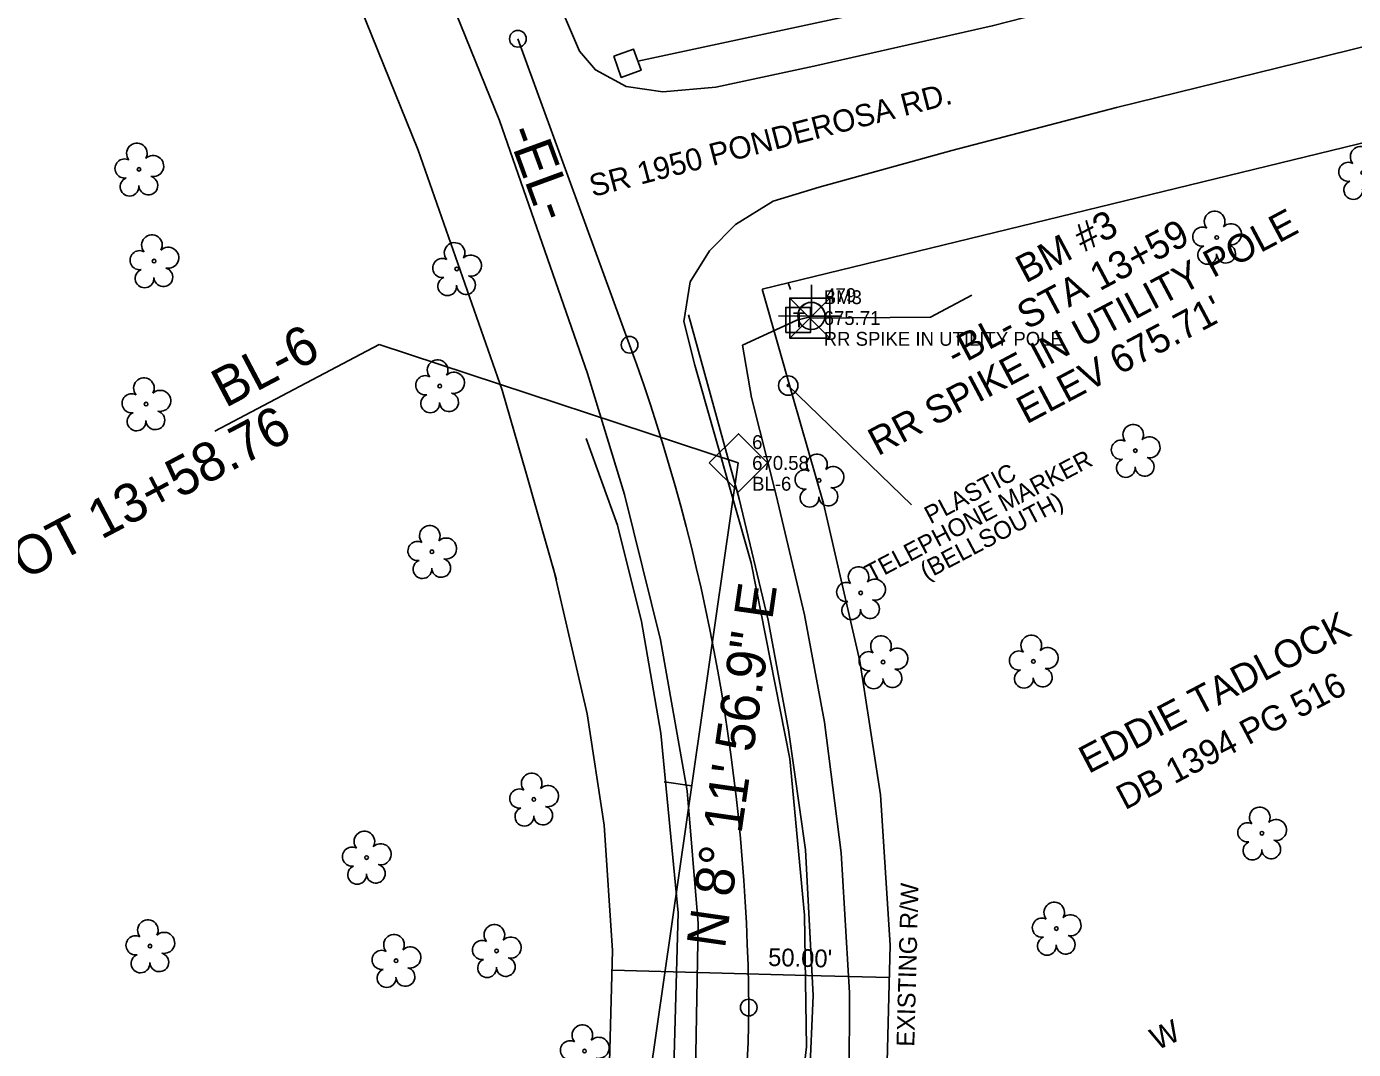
# Model space of a CAD drawing. Extents: x 1380524 to 1382335, y 594765 to 596944.
# Drawn here: x 1381752.4 to 1381991.4, y 595723.8 to 595908.1 of the extents above; entities that cross this region are included whole.
import ezdxf

# ---------------------------------------------------------------- set-up
doc = ezdxf.new("R2010")
doc.units = 0
for name, color, linetype in [('CTL Bench Mark CELL', 7, 'Continuous'), ('CTL Bench Mark Cogo Comment', 7, 'Continuous'), ('CTL Bench Mark Cogo Elevation', 7, 'Continuous'), ('CTL Bench Mark Cogo Number', 7, 'Continuous'), ('CTL Bench Mark Leader', 7, 'Continuous'), ('CTL Bench Mark Text', 7, 'Continuous'), ('CTL Supplemental Horizontal and Vertical Cogo Comment', 7, 'Continuous'), ('CTL Supplemental Horizontal and Vertical Cogo Elevation', 7, 'Continuous'), ('Exist Horizontal Alignment', 7, 'Continuous'), ('Exist Horizontal Alignment Direction Label', 7, 'Continuous'), ('Exist Horizontal Alignment Station Label', 7, 'Continuous'), ('Exist Horizontal Baseline Alignment', 7, 'Continuous'), ('Exist Horizontal Baseline Alignment Direction Label', 7, 'Continuous'), ('Exist Horizontal Baseline Alignment Station Label', 7, 'Continuous'), ('Exist Horizontal Baseline Alignment Tick small', 7, 'Continuous'), ('Exist Other Culture Fence Line', 7, 'Continuous'), ('Exist Other Culture Well Text', 7, 'Continuous'), ('Exist Right of Way Line', 7, 'Continuous'), ('Exist Right of Way Line Text', 7, 'Continuous'), ('Exist Roads EOP', 7, 'Continuous'), ('Exist Roads Soil', 7, 'Continuous'), ('Exist Structure Minor Pipes CMP 18 Inch', 7, 'Continuous'), ('Exist Utilities Gas UG Line SUE Text', 7, 'Continuous'), ('Exist Utilities Other Located Object Leader', 7, 'Continuous'), ('Exist Utilities Power Tower CELL', 7, 'Continuous'), ('Exist Utilities Telephone Pedestal CELL', 7, 'Continuous'), ('Exist Utilities Telephone UG Cable', 7, 'Continuous'), ('Exist Vegetation Tree CELL', 7, 'Continuous'), ('Exist Vertical Profile Vertical Axis Label', 7, 'Continuous'), ('Prop Drainage Ditch Flow Line', 7, 'Continuous'), ('Prop Drainage Structure Pipe Elbow Label', 7, 'Continuous'), ('Prop Earthen Structure Cut Ditch Special Detail CELL', 7, 'Continuous'), ('Prop Earthen Structure Ditch Flow Line', 7, 'Continuous'), ('Prop Erosion Rip Rap At Embankment Detail CELL', 7, 'Continuous'), ('Prop SS Cut Line', 7, 'Continuous'), ('Scratch_Level_6', 7, 'Continuous')]:
    doc.layers.add(name, color=color, linetype=linetype)

# ---------------------------------------------------------------- blocks, each defined once
blk = doc.blocks.new('EXIST VEGETATION TREE')
at = {"layer": 'Prop Erosion Rip Rap At Embankment Detail CELL'}
blk.add_line((0, 0), (0, 0), dxfattribs=at)
blk.add_circle((0, 0), 0.00652, dxfattribs=at)
for centre, radius, start, end in [((-0.0077, 0.0575), 0.0371, 330.1651, 219.7134), ((0.051, 0.0118), 0.038, 257.1011, 134.1999), ((-0.0521, 0.0031), 0.0345, 62.6636, 279.3457), ((-0.0341, -0.0624), 0.0338, 111.5671, 6.231), ((0.0335, -0.058), 0.034, 181.2822, 74.56)]:
    blk.add_arc(centre, radius, start, end, dxfattribs=at)
blk = doc.blocks.new('EXIST UTILITIES POWER JOINT USE TELEPHONE')
at = {"layer": 'Exist Utilities Gas UG Line SUE Text'}
blk.add_line((0, 0), (0, 0), dxfattribs=at)
blk.add_lwpolyline([(-0.1188, 0), (0.108, -0.0008), (0, -0.0004), (0, 0.1125)], dxfattribs=at)
blk.add_circle((0, 0.0001), 0.049, dxfattribs=at)
blk = doc.blocks.new('EXIST UTILITIES TELEPHONE PEDESTAL')
at = {"layer": 'Exist Utilities Telephone Pedestal CELL'}
blk.add_line((0, 0), (0, 0), dxfattribs=at)
blk.add_lwpolyline([(-0.0545, -0.0565), (0.0574, -0.0565), (0.0574, 0.0554), (-0.0545, 0.0554), (-0.0545, -0.0565)], dxfattribs=at)
blk.add_text('T', height=0.0684, dxfattribs=at).set_placement((-0.0226, -0.0343))
blk = doc.blocks.new('EXIST UTILITIES OTHER LOCATED OBJECT')
at = {"layer": 'Prop Earthen Structure Cut Ditch Special Detail CELL'}
for radius in [0.0436, 0.0048]:
    blk.add_circle((0, 0), radius, dxfattribs=at)

msp = doc.modelspace()

# ---------------------------------------------------------------- linework, layer by layer
at = {"layer": 'CTL Bench Mark CELL'}
msp.add_line((1381893.47, 595855.57), (1381893.47, 595855.57), dxfattribs=at)
msp.add_lwpolyline([(1381889.87, 595859.16), (1381897.06, 595859.16), (1381897.06, 595851.97), (1381889.87, 595851.97)], close=True, dxfattribs=at)
for points in [[(1381897.06, 595859.16), (1381889.87, 595851.97), (1381893.47, 595855.57), (1381897.06, 595851.97), (1381889.87, 595859.16)], [(1381893.47, 595855.57), (1381897.06, 595859.16), (1381889.87, 595859.16), (1381893.47, 595855.57)], [(1381893.47, 595855.57), (1381889.87, 595851.97), (1381897.06, 595851.97), (1381893.47, 595855.57)]]:
    msp.add_lwpolyline(points, dxfattribs=at)
at = {"layer": 'CTL Bench Mark Leader'}
msp.add_lwpolyline([(1381893.47, 595855.57), (1381915.22, 595855.75), (1381922.66, 595859.66)], dxfattribs=at)
at = {"layer": 'Exist Horizontal Alignment'}
msp.add_line((1381861, 595850.75), (1381840.88, 595905.87), dxfattribs=at)
msp.add_line((1381861, 595850.75), (1381840.88, 595905.87), dxfattribs=at)
msp.add_line((1381861, 595850.75), (1381840.88, 595905.87), dxfattribs=at)
msp.add_line((1381861, 595850.75), (1381840.88, 595905.87), dxfattribs=at)
msp.add_line((1381861, 595850.75), (1381840.88, 595905.87), dxfattribs=at)
for centre, radius, start, end in [((1381528.59, 595729.39), 353.88, 0.3204, 20.0563), ((1381528.59, 595729.39), 353.88, 0.3204, 20.0563), ((1381528.59, 595729.39), 353.88, 0.3204, 20.0563), ((1381732.46, 595730.53), 150, 321.7878, 0.3204), ((1381732.46, 595730.53), 150, 321.7878, 0.3204), ((1381732.46, 595730.53), 150, 321.7878, 0.3204)]:
    msp.add_arc(centre, radius, start, end, dxfattribs=at)
at = {"layer": 'Exist Horizontal Alignment Station Label'}
for centre in [(1381840.88, 595905.87), (1381861, 595850.75), (1381882.46, 595731.37)]:
    msp.add_circle(centre, 1.5, dxfattribs=at)
at = {"layer": 'Exist Horizontal Baseline Alignment'}
msp.add_line((1381849.7, 595615.17), (1381880.58, 595829.47), dxfattribs=at)
at = {"layer": 'Exist Horizontal Baseline Alignment Station Label'}
for p, q in [((1381815.89, 595850.81), (1381786.27, 595835.2)), ((1381880.58, 595829.47), (1381815.89, 595850.81))]:
    msp.add_line(p, q, dxfattribs=at)
at = {"layer": 'Exist Horizontal Baseline Alignment Tick small'}
msp.add_line((1381872.2, 595771.32), (1381867.25, 595772.03), dxfattribs=at)
at = {"layer": 'Exist Other Culture Fence Line'}
for q in [(1381893.75, 595861.56), (1381893.75, 595855.94)]:
    msp.add_line((1381893.75, 595855.94), q, dxfattribs=at)
msp.add_circle((1381893.75, 595855.94), 2.45, dxfattribs=at)
at = {"layer": 'Exist Roads EOP'}
for p, q in [((1381884.86, 595860.79), (1382255.74, 595951.12)), ((1381842.35, 595827.6), (1381838.07, 595842.58)), ((1381895.92, 595822.17), (1381890.42, 595841.37)), ((1381847.85, 595808.4), (1381842.35, 595827.6))]:
    msp.add_line(p, q, dxfattribs=at)
for points in [[(1381756.61, 596057.82), (1381792.83, 595960.19), (1381822.94, 595885.83), (1381838.07, 595842.58)], [(1381884.86, 595860.79), (1381890.42, 595841.37)], [(1381889.57, 595861.92), (1381889.98, 595860.73)], [(1381895.92, 595822.17), (1381902.47, 595793.76), (1381906.2, 595769.7), (1381907.97, 595742.61), (1381907.23, 595714.6), (1381902.73, 595686.65), (1381893.97, 595660.65), (1381884.45, 595642.32), (1381871.1, 595622.85), (1381855.36, 595606.07), (1381838.64, 595592.06), (1381819.68, 595578.62), (1381797.68, 595564.39), (1381777.69, 595551.91), (1381745.42, 595532.92), (1381704.18, 595509.33)], [(1381847.19, 595810.94), (1381853.34, 595784.3), (1381856.45, 595764.22), (1381857.93, 595741.64), (1381857.34, 595719.26), (1381854.03, 595698.69), (1381847.82, 595680.28), (1381841.48, 595668.07), (1381832.02, 595654.27), (1381820.95, 595642.47), (1381808.08, 595631.69), (1381791.64, 595620.03), (1381770.85, 595606.59), (1381751.76, 595594.66), (1381720.33, 595576.17), (1381679.35, 595552.72)]]:
    msp.add_lwpolyline(points, dxfattribs=at)
at = {"layer": 'Exist Utilities Other Located Object Leader'}
msp.add_lwpolyline([(1381889.58, 595843.41), (1381911.82, 595821.92)], dxfattribs=at)
at = {"layer": 'Exist Utilities Power Tower CELL'}
for p in [(1381857.84, 595738.09), (1381907.82, 595736.76)]:
    msp.add_line(p, (1381893.04, 595737.15), dxfattribs=at)
at = {"layer": 'Exist Utilities Telephone UG Cable'}
for p, q in [((1381880.73, 595823.01), (1381871.64, 595856.13)), ((1381891.13, 595855.21), (1381894.01, 595855.88)), ((1381881.35, 595850.66), (1381891.13, 595855.21)), ((1381882.97, 595841.27), (1381881.35, 595850.66)), ((1381887.4, 595823.66), (1381882.97, 595841.27)), ((1381858.83, 595818.25), (1381853.18, 595833.86)), ((1381885.96, 595801.15), (1381880.73, 595823.01)), ((1381892.51, 595802.1), (1381887.4, 595823.66)), ((1381863.12, 595800.9), (1381858.83, 595818.25)), ((1381866.66, 595780.77), (1381863.12, 595800.9)), ((1381889.63, 595781.4), (1381885.96, 595801.15)), ((1381896.12, 595782.79), (1381892.51, 595802.1)), ((1381892.7, 595759.75), (1381889.63, 595781.4)), ((1381899.13, 595759.23), (1381896.12, 595782.79)), ((1381869.73, 595748.41), (1381866.66, 595780.77)), ((1381894.08, 595733.51), (1381892.7, 595759.75)), ((1381900.64, 595734.04), (1381899.13, 595759.23)), ((1381868.99, 595720.53), (1381869.73, 595748.41)), ((1381892.86, 595705.57), (1381894.08, 595733.51)), ((1381900.56, 595709.92), (1381900.64, 595734.04))]:
    msp.add_line(p, q, dxfattribs=at)
at = {"layer": 'Prop Drainage Ditch Flow Line'}
msp.add_lwpolyline([(1381858.14, 595902.71), (1381861.72, 595903.98), (1381863.07, 595900.2), (1381859.49, 595898.92)], close=True, dxfattribs=at)
at = {"layer": 'Prop Drainage Structure Pipe Elbow Label'}
msp.add_lwpolyline([(1381862.51, 595901.85), (1381933.42, 595917.07)], dxfattribs=at)
at = {"layer": 'Prop Earthen Structure Ditch Flow Line'}
msp.add_line((1381860.1, 595823.76), (1381853.43, 595845.6), dxfattribs=at)
for points in [[(1381771.25, 596063.05), (1381807.38, 595965.66), (1381837.55, 595891.15), (1381853.43, 595845.6)], [(1382091.45, 595950.01), (1382040.09, 595937.29), (1382004.26, 595928.01), (1381958.8, 595916.53), (1381926.33, 595908.18), (1381894.21, 595900.91), (1381876.52, 595897.14), (1381867, 595896.29), (1381860.37, 595897.28), (1381854.86, 595900.27), (1381851.95, 595903.63), (1381839.95, 595931.67), (1381826.08, 595965.16), (1381814.38, 595994.56), (1381803.44, 596023.95), (1381793.75, 596050.62), (1381789.17, 596063.13)], [(1381875.4, 595867.69), (1381880.08, 595872.41), (1381886.87, 595876.59), (1381895.15, 595879.13), (1381919.07, 595885.76), (1381948.74, 595893.46), (1381985.14, 595902.41), (1382030.18, 595913.69), (1382063.68, 595922.37), (1382093.15, 595929.66)], [(1381695.4, 595522.74), (1381736.81, 595546.71), (1381778.65, 595571.33), (1381805.29, 595588.06), (1381825.76, 595602.01), (1381844.65, 595617.61), (1381860.52, 595635.43), (1381873.02, 595654.26), (1381883.82, 595678.23), (1381890.26, 595702.1), (1381892.88, 595724.32), (1381892.54, 595747.98), (1381889.9, 595776.18), (1381882.89, 595811.47), (1381872.74, 595847.05), (1381870.77, 595854.96), (1381871.9, 595862.06), (1381875.4, 595867.69)], [(1381686.7, 595538.62), (1381723.5, 595559.64), (1381752.33, 595576.66), (1381785.4, 595597.24), (1381806.72, 595611.59), (1381824.38, 595625.23), (1381839.64, 595640.2), (1381852.72, 595657.45), (1381860.22, 595671.32), (1381868.91, 595695.27), (1381872.89, 595719.75), (1381873.33, 595746.52), (1381871.37, 595770.38), (1381866.55, 595797.62), (1381860.1, 595823.76)]]:
    msp.add_lwpolyline(points, dxfattribs=at)
at = {"layer": 'Prop SS Cut Line'}
msp.add_line((1381880.58, 595829.47), (1381880.58, 595829.47), dxfattribs=at)
msp.add_lwpolyline([(1381875.36, 595829.49), (1381880.6, 595834.73), (1381885.85, 595829.48), (1381880.61, 595824.24)], close=True, dxfattribs=at)

# ---------------------------------------------------------------- block references
at = {"layer": 'Exist Utilities Gas UG Line SUE Text', "xscale": 50, "yscale": 50}
msp.add_blockref('EXIST UTILITIES POWER JOINT USE TELEPHONE', (1381893.75, 595855.94), dxfattribs=at)
at = {"layer": 'Exist Utilities Telephone Pedestal CELL', "xscale": 40, "yscale": 40}
msp.add_blockref('EXIST UTILITIES TELEPHONE PEDESTAL', (1381891.32, 595855.25), dxfattribs=at)
at = {"layer": 'Prop Earthen Structure Cut Ditch Special Detail CELL', "xscale": 40, "yscale": 40}
msp.add_blockref('EXIST UTILITIES OTHER LOCATED OBJECT', (1381889.58, 595843.41), dxfattribs=at)
at = {"layer": 'Prop Erosion Rip Rap At Embankment Detail CELL', "xscale": 50, "yscale": 50}
for p in [(1381772.62, 595882.35), (1381993.1, 595881.74), (1381966.79, 595870.07), (1381775.33, 595865.83), (1381829.86, 595864.42), (1381826.8, 595843.31), (1381773.89, 595840.06), (1381952.12, 595831.68), (1381895.14, 595826.32), (1381825.39, 595813.46), (1381902.64, 595806.05), (1381906.68, 595793.6), (1381933.76, 595793.72), (1381843.75, 595768.86), (1381974.92, 595762.76), (1381813.61, 595758.39), (1381937.89, 595745.6), (1381774.6, 595742.43), (1381837.03, 595741.58), (1381818.94, 595739.8), (1381852.88, 595723.52)]:
    msp.add_blockref('EXIST VEGETATION TREE', p, dxfattribs=at)

# ---------------------------------------------------------------- texts
at = {"layer": 'CTL Bench Mark Cogo Comment'}
msp.add_text('RR SPIKE IN UTILITY POLE', height=2.5, dxfattribs=at).set_placement((1381895.97, 595850.57))
at = {"layer": 'CTL Bench Mark Cogo Elevation'}
msp.add_text('675.71', height=2.5, dxfattribs=at).set_placement((1381895.97, 595854.32))
at = {"layer": 'CTL Bench Mark Cogo Number'}
msp.add_text('BM3', height=2.5, dxfattribs=at).set_placement((1381895.97, 595858.07))
at = {"layer": 'CTL Bench Mark Text'}
for s, p in [('RR SPIKE IN UTILITY POLE', (1381905.73, 595830.65)), ('BM #3 ', (1381932.34, 595861.76)), ('-BL- STA 13+59', (1381919.75, 595846.59)), ("ELEV 675.71'", (1381932.49, 595836.37))]:
    msp.add_text(s, height=5, rotation=27.9689, dxfattribs=at).set_placement(p)
at = {"layer": 'CTL Supplemental Horizontal and Vertical Cogo Comment'}
msp.add_text('BL-6', height=2.5, dxfattribs=at).set_placement((1381883.08, 595824.47))
at = {"layer": 'CTL Supplemental Horizontal and Vertical Cogo Elevation'}
msp.add_text('670.58', height=2.5, dxfattribs=at).set_placement((1381883.08, 595828.22))
at = {"layer": 'Exist Horizontal Alignment Direction Label'}
msp.add_text('-EL-', height=7, rotation=290.0563, dxfattribs=at).set_placement((1381838.82, 595889.11))
at = {"layer": 'Exist Horizontal Baseline Alignment Direction Label'}
msp.add_text('N 8%%d 11\' 56.9" E', height=7, rotation=81.8009, dxfattribs=at).set_placement((1381878.16, 595741.83))
at = {"layer": 'Exist Horizontal Baseline Alignment Station Label'}
msp.add_text('BL-6', height=7, rotation=27.7977, dxfattribs=at).set_placement((1381788.16, 595839.3))
at = {"layer": 'Exist Other Culture Well Text'}
msp.add_text('W', height=4, rotation=25, dxfattribs=at).set_placement((1381956, 595723.59))
at = {"layer": 'Exist Right of Way Line'}
msp.add_text('EDDIE TADLOCK', height=5, rotation=27.7614, dxfattribs=at).set_placement((1381943.69, 595773.41))
at = {"layer": 'Exist Right of Way Line Text'}
msp.add_text('EXISTING R/W', height=3.2, rotation=88.4793, dxfattribs=at).set_placement((1381912.29, 595724.29))
at = {"layer": 'Exist Roads Soil'}
msp.add_text('6', height=2.5, dxfattribs=at).set_placement((1381883.08, 595831.97))
at = {"layer": 'Exist Structure Minor Pipes CMP 18 Inch'}
msp.add_text('DB 1394 PG 516', height=4.5, rotation=27.7614, dxfattribs=at).set_placement((1381950.26, 595766.88))
at = {"layer": 'Exist Utilities Power Tower CELL'}
msp.add_text("50.00'", height=3.2, rotation=358.4793, dxfattribs=at).set_placement((1381885.93, 595738.87))
at = {"layer": 'Exist Vegetation Tree CELL'}
msp.add_text('479', height=2.5, dxfattribs=at).set_placement((1381896.25, 595858.44))
msp.add_text('479', height=2.5, dxfattribs=at).set_placement((1381896.25, 595858.44))
at = {"layer": 'Exist Vertical Profile Vertical Axis Label'}
msp.add_text('SR 1950 PONDEROSA RD.', height=4, rotation=14.556, dxfattribs=at).set_placement((1381854.35, 595877.34))
at = {"layer": 'Prop Earthen Structure Cut Ditch Special Detail CELL'}
for s, p in [('TELEPHONE MARKER', (1381904.54, 595807.94)), ('PLASTIC', (1381915.21, 595818.39)), ('(BELLSOUTH)', (1381914.44, 595808.34))]:
    msp.add_text(s, height=3.2, rotation=27.7977, dxfattribs=at).set_placement(p)
at = {"layer": 'Scratch_Level_6'}
msp.add_text('-BL- POT 13+58.76 ', height=7, rotation=27.7977, dxfattribs=at).set_placement((1381728.54, 595795.94))

doc.saveas('drawing.dxf')
